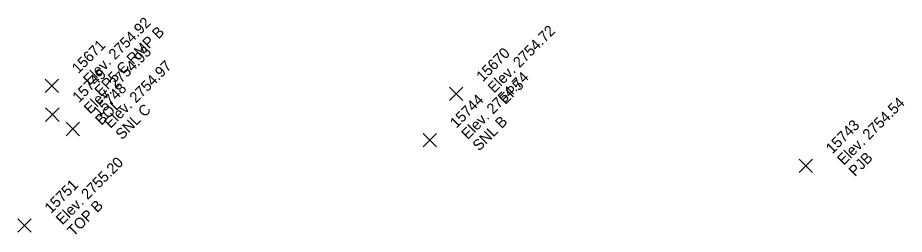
# Model space of a CAD drawing. Extents: x 2493999 to 2503109, y 700767 to 706646.
# Drawn here: x 2502242.22 to 2502262.09, y 704032.72 to 704037.57 of the extents above; entities that cross this region are included whole.
import ezdxf

# ---------------------------------------------------------------- set-up
doc = ezdxf.new("R2010")
doc.units = 0
doc.layers.add('ALG_CL_BLUE_Horiz', color=7, linetype='Continuous')
doc.layers.add('DES_SURFACE_Existing-Ground', color=7, linetype='Continuous')

msp = doc.modelspace()

# ---------------------------------------------------------------- linework, layer by layer
at = {"layer": 'ALG_CL_BLUE_Horiz'}
for points in [[(2502242.98, 704036.045), (2502242.83, 704036.195), (2502242.98, 704036.045), (2502242.83, 704035.895), (2502242.98, 704036.045), (2502243.13, 704035.895), (2502242.98, 704036.045), (2502243.13, 704036.195)], [(2502252.046, 704035.865), (2502251.896, 704036.015), (2502252.046, 704035.865), (2502251.896, 704035.715), (2502252.046, 704035.865), (2502252.196, 704035.715), (2502252.046, 704035.865), (2502252.196, 704036.015)], [(2502242.993, 704035.397), (2502242.843, 704035.547), (2502242.993, 704035.397), (2502242.843, 704035.247), (2502242.993, 704035.397), (2502243.143, 704035.247), (2502242.993, 704035.397), (2502243.143, 704035.547)], [(2502243.45, 704035.076), (2502243.3, 704035.226), (2502243.45, 704035.076), (2502243.3, 704034.926), (2502243.45, 704035.076), (2502243.6, 704034.926), (2502243.45, 704035.076), (2502243.6, 704035.226)], [(2502251.455, 704034.823), (2502251.305, 704034.973), (2502251.455, 704034.823), (2502251.305, 704034.673), (2502251.455, 704034.823), (2502251.605, 704034.673), (2502251.455, 704034.823), (2502251.605, 704034.973)], [(2502259.882, 704034.251), (2502259.732, 704034.401), (2502259.882, 704034.251), (2502259.732, 704034.101), (2502259.882, 704034.251), (2502260.032, 704034.101), (2502259.882, 704034.251), (2502260.032, 704034.401)], [(2502242.367, 704032.914), (2502242.217, 704033.064), (2502242.367, 704032.914), (2502242.217, 704032.764), (2502242.367, 704032.914), (2502242.517, 704032.764), (2502242.367, 704032.914), (2502242.517, 704033.064)]]:
    msp.add_lwpolyline(points, dxfattribs=at)

# ---------------------------------------------------------------- texts
at = {"layer": 'DES_SURFACE_Existing-Ground'}
for s, p in [('Elev. 2754.92', (2502243.829, 704036.045)), ('EP5 C RMP B', (2502244.083, 704035.79)), ('Elev. 2754.72', (2502252.895, 704035.865)), ('15671', (2502243.574, 704036.3)), ('Elev. 2754.93', (2502243.842, 704035.397)), ('15670', (2502252.64, 704036.12)), ('Elev. 2754.97', (2502244.299, 704035.076)), ('15749', (2502243.587, 704035.652)), ('Elev. 2754.74', (2502252.304, 704034.823)), ('15748', (2502244.044, 704035.331)), ('EP5', (2502253.149, 704035.61)), ('15744', (2502252.049, 704035.078)), ('BOL', (2502244.096, 704035.142)), ('Elev. 2754.54', (2502260.731, 704034.251)), ('SNL C', (2502244.553, 704034.821)), ('SNL B', (2502252.558, 704034.568)), ('15743', (2502260.476, 704034.506)), ('PJB', (2502260.985, 704033.996)), ('Elev. 2755.20', (2502243.216, 704032.914)), ('15751', (2502242.961, 704033.169)), ('TOP B', (2502243.47, 704032.659))]:
    msp.add_text(s, height=0.24, rotation=45, dxfattribs=at).set_placement(p)

doc.saveas('drawing.dxf')
